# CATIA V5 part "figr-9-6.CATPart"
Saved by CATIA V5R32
Part number: Part2
Bounding box of the stored display mesh (mm): x -75 to 75, y -75 to 96.278, z -26.878 to 0
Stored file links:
  D:\PROJECTS\Project 2022\CATIA V5 6R 2022\Resources\Part Files\c09_catia_v5_6r2022_prt\c09_catia_v5_6r2022_prt\figr-9-6.CATPart
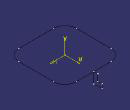
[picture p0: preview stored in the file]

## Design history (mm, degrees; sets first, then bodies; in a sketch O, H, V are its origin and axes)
Body1 (main body)
  Sketch1 on xy-plane, origin (0, 0, 0), H (1, 0, 0), V (0, 1, 0)
    point P1 (-75, 75)
    line L1 (-45, 75) -> (45, 75)
    line L2 (75, 45) -> (75, -45)
    line L3 (45, -75) -> (-45, -75)
    line L4 (-75, -45) -> (-75, 45)
    point P2 (75, 75)
    point P3 (75, -75)
    point P4 (-75, -75)
    axis line L5 (75, -75) -> (-75, 75)
    arc A1 centre (45, -45) radius 30 from (75, -45) to (45, -75) cw
    arc A2 centre (45, 45) radius 30 from (45, 75) to (75, 45) cw
    arc A3 centre (-45, 45) radius 30 from (-45, 75) to (-75, 45) ccw
    arc A4 centre (-45, -45) radius 30 from (-45, -75) to (-75, -45) cw
    distance P2 P3 = 150
    distance P3 P4 = 150
    radius A1 = 30
    radius A2 = 30
    radius A3 = 30
    radius A4 = 30
    horizontal: L1 H, L3 H
    vertical: L2 V, L4 V
    midpoint: O L5
    coincidence: L2 P3, L3 P3, L1 P2, L2 P2, L1 P1, L4 P1, L3 P4, L4 P4
    tangency: A1 L2, A1 L3, A2 L1, A2 L2, A3 L1, A3 L4, A4 L3, A4 L4
  Sketch2 on yz-plane, origin (0, 0, 0), H (0, 1, 0), V (0, 0, 1)
    point P1 (85, 0)
    line L1 (85, 0) -> (85, -16.8782)
    line L2 (85, -16.8782) -> (96.2781, -16.8782)
    line L3 (96.2781, -16.8782) -> (96.2781, -26.8782)
    line L4 (96.2781, -26.8782) -> (75, -26.8782)
    line L5 (75, -26.8782) -> (75, 0)
    point P6 (75, 0)
    line L6 (75, 0) -> (85, 0)
    reference projected point E1 (75, 0) from edge of Sketch1
    length L3 = 10
    length L6 = 10
    coincidence: P1 H, P6 H, P6 E1
    vertical: L1 V, L3 V, L5 V
    horizontal: L2 H, L4 H, L6 H
  Rib1: profile Sketch2, centre curve Sketch1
